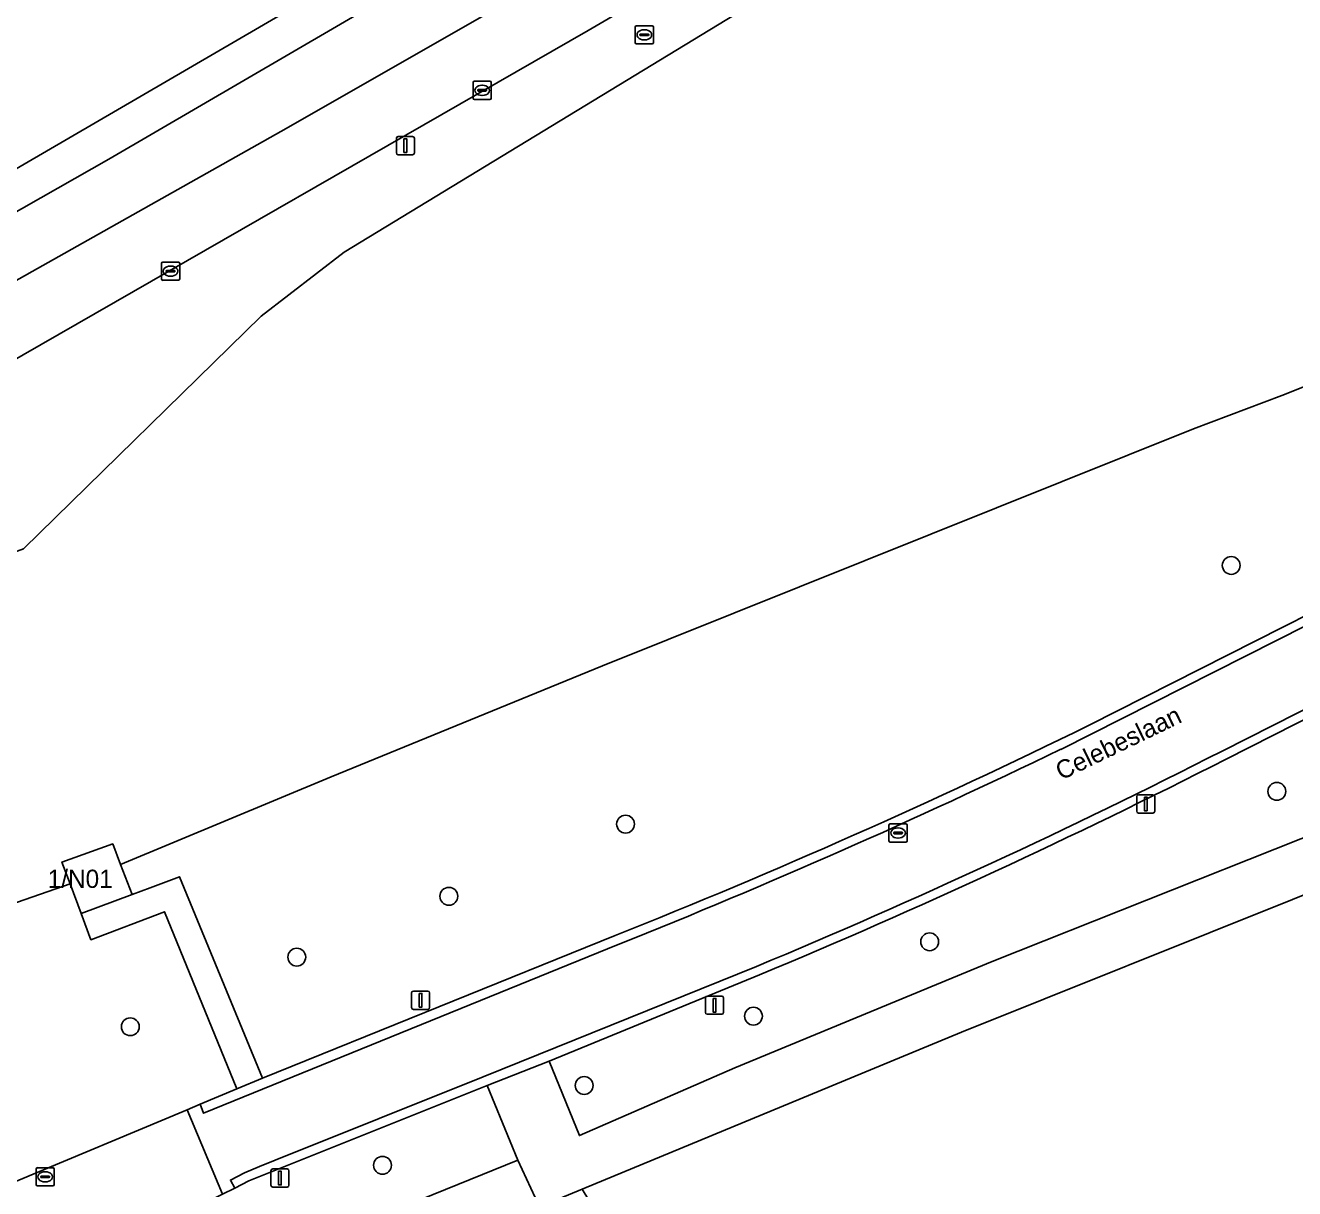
# Model space of a CAD drawing. Extents: x 162879 to 165540, y 384011 to 385181.
# Drawn here: x 163061.1 to 163130.7, y 384259.7 to 384323.5 of the extents above; entities that cross this region are included whole.
import ezdxf

# ---------------------------------------------------------------- set-up
doc = ezdxf.new("R2010")
doc.units = 0
for name, color, linetype in [('IMGEO_Berm_groen', 7, 'Continuous'), ('IMGEO_Boom', 7, 'Continuous'), ('IMGEO_Groenvoorziening', 7, 'Continuous'), ('IMGEO_Kolk', 7, 'Continuous'), ('IMGEO_Lichtmast', 7, 'Continuous'), ('IMGEO_Loofbos', 7, 'Continuous'), ('IMGEO_Openbare_ruimte_label', 7, 'Continuous'), ('IMGEO_Pand', 7, 'Continuous'), ('IMGEO_Pand_nummerreeks', 7, 'Continuous'), ('IMGEO_Rijbaan_lokaal_gesloten', 7, 'Continuous'), ('IMGEO_Rijbaan_lokaal_open', 7, 'Continuous'), ('IMGEO_Rijbaan_regionaal_gesloten', 7, 'Continuous'), ('IMGEO_Rioolput', 7, 'Continuous'), ('IMGEO_Verkeersbordpaal', 7, 'Continuous'), ('IMGEO_Voetpad_open', 7, 'Continuous')]:
    doc.layers.add(name, color=color, linetype=linetype)

msp = doc.modelspace()

# ---------------------------------------------------------------- linework, layer by layer
at = {"layer": 'IMGEO_Berm_groen'}
for points in [[(162958.296, 384257.287), (162992.107, 384275.576), (162992.774, 384275.937), (163000, 384279.879), (163047.71, 384305.906), (163065.69, 384316.128), (163134.875, 384356.468), (163142.16, 384360.715), (163149.867, 384365.229), (163197.962, 384393.395), (163222.445, 384407.821), (163353.264, 384484.905)], [(163146.789, 384293.17), (163146.364, 384293.038), (163145.533, 384292.61), (163143.634, 384291.66), (163126.98, 384283.214)], [(163101.395, 384271.38), (163089.844, 384266.648), (163091.511, 384262.562), (163100.027, 384266.274), (163114.146, 384272.104), (163148.014, 384285.572)]]:
    msp.add_lwpolyline(points, dxfattribs=at)
msp.add_lwpolyline([(163148.842, 384366.976), (163055.696, 384312.747), (162991.211, 384277.349), (162986.763, 384286.167), (162986.414, 384294.29), (162999.918, 384301.631), (163052.601, 384331.084), (163140.211, 384381.691)], close=True, dxfattribs=at)
msp.add_arc((162961.197, 384608.061), 364.705, 292.60743, 297.03711, dxfattribs=at)
at = {"layer": 'IMGEO_Boom'}
for centre in [(163127.263, 384293.838), (163129.763, 384281.443), (163094.039, 384279.646), (163084.348, 384275.687), (163110.72, 384273.192), (163076.004, 384272.35), (163101.054, 384269.112), (163066.872, 384268.531), (163091.77, 384265.308), (163080.708, 384260.93)]:
    msp.add_circle(centre, 0.489, dxfattribs=at)
at = {"layer": 'IMGEO_Groenvoorziening'}
for points in [[(163596.733, 384620.336), (163590.474, 384616.677), (163584.15, 384613.033), (163543.932, 384589.276), (163500, 384563.326), (163392.794, 384500), (163356.886, 384478.81), (163202.966, 384387.982), (163138.189, 384350.166), (163091.98, 384323.19), (163060.001, 384304.827), (163000, 384271.727), (162995.148, 384269.194), (162989.657, 384266.154), (162987.354, 384264.896)], [(162987.751, 384263.155), (162988.941, 384263.017), (163012.114, 384262.491), (163015.053, 384262.437), (163010.306, 384266.101), (163010.259, 384272.54), (163015.983, 384275.987), (163044.781, 384289.14), (163054.546, 384290.508), (163057.113, 384293.326), (163061.012, 384294.747), (163074.049, 384307.518), (163078.609, 384311.03), (163103.227, 384326.016), (163139.713, 384347.269), (163141.708, 384348.431), (163145.603, 384350.692), (163147.412, 384351.742), (163229.097, 384399.154), (163272.33, 384424.447), (163305.16, 384443.366)], [(163166.298, 384308.662), (163164.771, 384310.215), (163162.156, 384313.029), (163158.27, 384312.081), (163155.41, 384311.383), (163152.808, 384310.825), (163143.627, 384308.496), (163140.765, 384307.422), (163130.038, 384303.169), (163125.187, 384301.331), (163092.767, 384288.329), (163077.888, 384282.235), (163066.344, 384277.423), (163066.971, 384275.787), (163067.96, 384276.156), (163069.579, 384276.761), (163074.126, 384265.704), (163093.473, 384273.529)], [(163119.462, 384285.067), (163142.305, 384296.633), (163150.718, 384300.902)], [(163072.715, 384265.119), (163068.75, 384274.837), (163064.714, 384273.307), (163064.181, 384274.747), (163063.569, 384276.375), (163023.085, 384262.29), (163033.666, 384262.096), (163044.189, 384261.925), (163045.835, 384261.901), (163046.653, 384261.889)], [(163060.533, 384260.029), (163069.992, 384263.975), (163070.704, 384264.278), (163072.715, 384265.119)], [(163088.136, 384261.216), (163086.443, 384265.31), (163074.285, 384260.44), (163073.374, 384260.069), (163072.602, 384259.676), (163071.935, 384259.339), (163070.11, 384258.418), (163069.325, 384258.023), (163069.104, 384257.867)], [(163066.874, 384252.737), (163069.054, 384253.483), (163088.136, 384261.216)]]:
    msp.add_lwpolyline(points, dxfattribs=at)
msp.add_arc((162954.46, 384621.689), 374.887, 291.76571, 296.11262, dxfattribs=at)
at = {"layer": 'IMGEO_Kolk'}
for p, q in [((163085.672, 384319.474), (163085.672, 384320.326)), ((163085.747, 384320.4), (163086.599, 384320.4)), ((163086.16, 384320.18), (163086.185, 384320.18)), ((163086.673, 384320.326), (163086.673, 384319.474)), ((163086.599, 384319.4), (163085.747, 384319.4)), ((163085.931, 384319.894), (163085.931, 384319.906)), ((163086.369, 384319.857), (163085.971, 384319.857)), ((163085.974, 384319.943), (163086.372, 384319.943)), ((163086.183, 384319.62), (163086.158, 384319.62)), ((163086.415, 384319.906), (163086.415, 384319.894)), ((163068.582, 384309.553), (163068.582, 384310.405)), ((163068.657, 384310.479), (163069.509, 384310.479)), ((163069.583, 384310.405), (163069.583, 384309.553)), ((163068.841, 384309.973), (163068.841, 384309.985)), ((163069.279, 384309.936), (163068.881, 384309.936)), ((163068.884, 384310.022), (163069.282, 384310.022)), ((163069.093, 384309.699), (163069.068, 384309.699)), ((163069.07, 384310.259), (163069.095, 384310.259)), ((163069.325, 384309.985), (163069.325, 384309.973)), ((163069.509, 384309.479), (163068.657, 384309.479))]:
    msp.add_line(p, q, dxfattribs=at)
for points in [[(163085.672, 384319.474), (163085.672, 384320.326)], [(163085.747, 384320.4), (163086.599, 384320.4)], [(163086.673, 384320.326), (163086.673, 384319.474)], [(163086.599, 384319.4), (163085.747, 384319.4)], [(163068.582, 384309.553), (163068.582, 384310.405)], [(163068.657, 384310.479), (163069.509, 384310.479)], [(163069.583, 384310.405), (163069.583, 384309.553)], [(163069.509, 384309.479), (163068.657, 384309.479)]]:
    msp.add_lwpolyline(points, dxfattribs=at)
for centre, radius, start, end in [((163085.749, 384320.324), 0.0765, 91.55205, 178.44795), ((163085.749, 384320.324), 0.0765, 91.55205, 178.44795), ((163086.597, 384320.324), 0.0765, 1.55205, 88.44795), ((163086.597, 384320.324), 0.0765, 1.55205, 88.44795), ((163085.749, 384319.476), 0.0765, 181.55205, 268.44795), ((163085.749, 384319.476), 0.0765, 181.55205, 268.44795), ((163085.971, 384319.903), 0.0403, 85.87752, 175.75265), ((163085.968, 384319.893), 0.0366, 178.93798, 274.71019), ((163086.372, 384319.9), 0.043, 264.86636, 352.45326), ((163086.376, 384319.905), 0.0386, 1.73085, 96.63898), ((163086.597, 384319.476), 0.0765, 271.55205, 358.44795), ((163086.597, 384319.476), 0.0765, 271.55205, 358.44795), ((163068.659, 384310.403), 0.0765, 91.55205, 178.44795), ((163068.659, 384310.403), 0.0765, 91.55205, 178.44795), ((163069.507, 384310.403), 0.0765, 1.55205, 88.44795), ((163069.507, 384310.403), 0.0765, 1.55205, 88.44795), ((163068.881, 384309.982), 0.0403, 85.87752, 175.75265), ((163068.878, 384309.972), 0.0366, 178.93798, 274.71019), ((163069.282, 384309.979), 0.043, 264.86636, 352.45326), ((163069.286, 384309.984), 0.0386, 1.73085, 96.63898), ((163068.659, 384309.555), 0.0765, 181.55205, 268.44795), ((163068.659, 384309.555), 0.0765, 181.55205, 268.44795), ((163069.507, 384309.555), 0.0765, 271.55205, 358.44795), ((163069.507, 384309.555), 0.0765, 271.55205, 358.44795)]:
    msp.add_arc(centre, radius, start, end, dxfattribs=at)
for centre, major_axis, ratio, start_param, end_param in [((163086.159, 384319.9), (-0.387, 0.002), 0.722429, 4.712389, 7.853982), ((163086.184, 384319.9), (-0.39, 0.002), 0.717154, 1.570796, 4.712389), ((163069.069, 384309.979), (-0.387, 0.002), 0.722429, 4.712389, 7.853982), ((163069.094, 384309.979), (-0.39, 0.002), 0.717154, 1.570796, 4.712389)]:
    msp.add_ellipse(centre, major_axis=major_axis, ratio=ratio, start_param=start_param, end_param=end_param, dxfattribs=at)
at = {"layer": 'IMGEO_Lichtmast'}
for p, q in [((163081.566, 384317.37), (163082.356, 384317.37)), ((163082.356, 384317.37), (163081.566, 384317.37)), ((163081.466, 384316.47), (163081.466, 384317.27)), ((163081.466, 384317.27), (163081.466, 384316.47)), ((163082.456, 384317.27), (163082.456, 384316.47)), ((163082.456, 384316.47), (163082.456, 384317.27)), ((163082.356, 384316.37), (163081.566, 384316.37)), ((163081.566, 384316.37), (163082.356, 384316.37)), ((163122.081, 384280.356), (163122.081, 384281.156)), ((163122.081, 384281.156), (163122.081, 384280.356)), ((163122.181, 384281.256), (163122.971, 384281.256)), ((163122.971, 384281.256), (163122.181, 384281.256)), ((163123.071, 384281.156), (163123.071, 384280.356)), ((163123.071, 384280.356), (163123.071, 384281.156)), ((163122.971, 384280.256), (163122.181, 384280.256)), ((163122.181, 384280.256), (163122.971, 384280.256)), ((163098.422, 384269.312), (163098.422, 384270.112)), ((163098.422, 384270.112), (163098.422, 384269.312)), ((163098.522, 384270.212), (163099.312, 384270.212)), ((163099.312, 384270.212), (163098.522, 384270.212)), ((163099.412, 384270.112), (163099.412, 384269.312)), ((163099.412, 384269.312), (163099.412, 384270.112)), ((163099.312, 384269.212), (163098.522, 384269.212)), ((163098.522, 384269.212), (163099.312, 384269.212)), ((163074.587, 384259.832), (163074.587, 384260.632)), ((163074.587, 384260.632), (163074.587, 384259.832)), ((163074.687, 384260.732), (163075.477, 384260.732)), ((163075.477, 384260.732), (163074.687, 384260.732)), ((163075.577, 384260.632), (163075.577, 384259.832)), ((163075.577, 384259.832), (163075.577, 384260.632)), ((163075.477, 384259.732), (163074.687, 384259.732)), ((163074.687, 384259.732), (163075.477, 384259.732))]:
    msp.add_line(p, q, dxfattribs=at)
for points in [[(163081.886, 384317.245), (163082.036, 384317.245), (163082.036, 384316.495), (163081.886, 384316.495), (163081.886, 384317.245)], [(163122.501, 384281.131), (163122.651, 384281.131), (163122.651, 384280.381), (163122.501, 384280.381), (163122.501, 384281.131)], [(163098.842, 384270.087), (163098.992, 384270.087), (163098.992, 384269.337), (163098.842, 384269.337), (163098.842, 384270.087)], [(163075.007, 384260.607), (163075.157, 384260.607), (163075.157, 384259.857), (163075.007, 384259.857), (163075.007, 384260.607)]]:
    msp.add_lwpolyline(points, dxfattribs=at)
for centre, start, end in [((163081.566, 384317.27), 90, 180), ((163081.566, 384317.27), 90, 180), ((163082.356, 384317.27), 0, 90), ((163082.356, 384317.27), 360, 90), ((163081.566, 384316.47), 180, 270), ((163081.566, 384316.47), 180, 270), ((163082.356, 384316.47), 270, 0), ((163082.356, 384316.47), 270, 0), ((163122.181, 384281.156), 90, 180), ((163122.181, 384281.156), 90, 180), ((163122.971, 384281.156), 0, 90), ((163122.971, 384281.156), 360, 90), ((163122.181, 384280.356), 180, 270), ((163122.181, 384280.356), 180, 270), ((163122.971, 384280.356), 270, 0), ((163122.971, 384280.356), 270, 0), ((163098.522, 384270.112), 90, 180), ((163098.522, 384270.112), 90, 180), ((163099.312, 384270.112), 0, 90), ((163099.312, 384270.112), 360, 90), ((163098.522, 384269.312), 180, 270), ((163098.522, 384269.312), 180, 270), ((163099.312, 384269.312), 270, 0), ((163099.312, 384269.312), 270, 0), ((163074.687, 384260.632), 90, 180), ((163074.687, 384260.632), 90, 180), ((163075.477, 384260.632), 0, 90), ((163075.477, 384260.632), 360, 90), ((163074.687, 384259.832), 180, 270), ((163074.687, 384259.832), 180, 270), ((163075.477, 384259.832), 270, 0), ((163075.477, 384259.832), 270, 0)]:
    msp.add_arc(centre, 0.1, start, end, dxfattribs=at)
at = {"layer": 'IMGEO_Loofbos'}
for points in [[(163140.211, 384381.691), (163052.601, 384331.084), (162999.918, 384301.631), (162986.414, 384294.29), (162986.763, 384286.167), (162991.211, 384277.349), (163055.696, 384312.747), (163148.842, 384366.976)], [(163155.934, 384258.131), (163155.116, 384260.952), (163148.784, 384282.785), (163112.465, 384268.23), (163091.662, 384259.624), (163097.491, 384250), (163105.946, 384236.061), (163109.025, 384230.235), (163114.501, 384233.625), (163136.641, 384247.33), (163140.262, 384250), (163143.861, 384252.646)]]:
    msp.add_lwpolyline(points, close=True, dxfattribs=at)
msp.add_lwpolyline([(163139.713, 384347.269), (163103.227, 384326.016), (163078.609, 384311.03), (163074.049, 384307.518), (163061.012, 384294.747), (163057.113, 384293.326), (163054.546, 384290.508), (163044.781, 384289.14), (163015.983, 384275.987), (163010.259, 384272.54), (163010.306, 384266.101), (163015.053, 384262.437), (163023.085, 384262.29), (163063.569, 384276.375), (163063.122, 384277.562), (163065.907, 384278.563), (163066.344, 384277.423), (163077.888, 384282.235), (163092.767, 384288.329), (163125.187, 384301.331), (163130.038, 384303.169), (163140.765, 384307.422)], dxfattribs=at)
at = {"layer": 'IMGEO_Pand'}
msp.add_lwpolyline([(163066.344, 384277.423), (163065.907, 384278.563), (163063.122, 384277.562), (163063.569, 384276.375), (163064.181, 384274.747), (163066.971, 384275.787)], close=True, dxfattribs=at)
at = {"layer": 'IMGEO_Rijbaan_lokaal_gesloten'}
for points in [[(163143.365, 384292.054), (163141.531, 384295.681), (163117.918, 384283.749)], [(163126.767, 384283.656), (163143.365, 384292.054)], [(163093.642, 384273.04), (163070.882, 384263.789), (163070.704, 384264.278), (163069.992, 384263.975), (163071.935, 384259.339), (163072.602, 384259.676), (163072.365, 384260.115), (163073.136, 384260.517), (163073.968, 384260.869), (163074.82, 384261.212), (163086.237, 384265.783), (163101.219, 384271.839)]]:
    msp.add_lwpolyline(points, dxfattribs=at)
msp.add_lwpolyline([(163069.325, 384258.023), (163070.11, 384258.418), (163071.935, 384259.339), (163069.992, 384263.975), (163060.533, 384260.029), (163050.998, 384256.102), (163049.129, 384255.319), (163048.235, 384254.869), (163047.128, 384254.295), (163035.025, 384248.253), (163031.406, 384246.417), (163034.42, 384240.509), (163038.44, 384242.526), (163056.687, 384251.652)], close=True, dxfattribs=at)
for centre, radius, start, end in [((162951.566, 384627.979), 382.318, 291.81539, 295.79255), ((162961.001, 384608.513), 364.706, 292.61084, 297.03412)]:
    msp.add_arc(centre, radius, start, end, dxfattribs=at)
at = {"layer": 'IMGEO_Rijbaan_lokaal_open'}
for points in [[(163161.368, 384306.288), (163152.507, 384301.843), (163150.718, 384300.902), (163142.305, 384296.633), (163119.462, 384285.067)], [(163172.552, 384306.5), (163164.703, 384302.899), (163163.382, 384302.252), (163162.739, 384301.938), (163159.882, 384300.503), (163153.951, 384297.527), (163152.765, 384296.875), (163143.423, 384292.083), (163143.365, 384292.054), (163126.767, 384283.656)], [(163117.918, 384283.749), (163141.531, 384295.681), (163150.915, 384300.439), (163152.679, 384301.369), (163161.622, 384305.861)], [(163126.98, 384283.214), (163143.634, 384291.66)], [(163093.473, 384273.529), (163074.126, 384265.704), (163072.715, 384265.119), (163070.704, 384264.278), (163070.882, 384263.789), (163093.642, 384273.04)], [(163101.219, 384271.839), (163086.237, 384265.783), (163074.82, 384261.212), (163073.968, 384260.869), (163073.136, 384260.517), (163072.365, 384260.115), (163072.602, 384259.676), (163073.374, 384260.069), (163074.285, 384260.44), (163086.443, 384265.31), (163089.844, 384266.648), (163101.395, 384271.38)]]:
    msp.add_lwpolyline(points, dxfattribs=at)
for centre, radius, start, end in [((162954.46, 384621.689), 374.887, 291.76571, 296.11262), ((162951.566, 384627.979), 382.318, 291.81539, 295.79255), ((162961.001, 384608.513), 364.706, 292.61084, 297.03412), ((162961.197, 384608.061), 364.705, 292.60743, 297.03711)]:
    msp.add_arc(centre, radius, start, end, dxfattribs=at)
at = {"layer": 'IMGEO_Rijbaan_regionaal_gesloten'}
for points in [[(163075.431, 384317.808), (163102.908, 384333.537), (163136.085, 384353.074), (163136.524, 384353.333), (163134.875, 384356.468), (163065.69, 384316.128), (163047.71, 384305.906), (163000, 384279.879), (162992.774, 384275.937), (162992.107, 384275.576), (162958.296, 384257.287)], [(163060.001, 384304.827), (163091.98, 384323.19), (163138.189, 384350.166), (163136.524, 384353.333), (163136.085, 384353.074), (163102.908, 384333.537), (163075.431, 384317.808), (163019.119, 384286.121), (162984.518, 384267.432), (162966.682, 384257.842), (162956.166, 384251.683), (162950.166, 384247.581), (162946.914, 384245.082), (162943.802, 384242.49), (162940.823, 384239.608), (162938.038, 384236.628), (162940.725, 384234.294)], [(162937.637, 384241.374), (162932.679, 384236.006), (162916.515, 384218.506), (162915.908, 384217.643), (162913.326, 384214.826), (162913.538, 384209.756), (162921.56, 384218.689), (162929.746, 384227.688), (162935.296, 384233.694), (162938.038, 384236.628), (162940.823, 384239.608), (162943.802, 384242.49), (162946.914, 384245.082), (162950.166, 384247.581), (162956.166, 384251.683), (162966.682, 384257.842), (162984.518, 384267.432), (163019.119, 384286.121), (163075.431, 384317.808)]]:
    msp.add_lwpolyline(points, dxfattribs=at)
at = {"layer": 'IMGEO_Rioolput'}
for p, q in [((163094.569, 384322.522), (163094.569, 384323.374)), ((163094.644, 384323.448), (163095.496, 384323.448)), ((163094.828, 384322.942), (163094.828, 384322.954)), ((163095.266, 384322.905), (163094.868, 384322.905)), ((163094.871, 384322.991), (163095.269, 384322.991)), ((163095.057, 384323.228), (163095.082, 384323.228)), ((163095.312, 384322.954), (163095.312, 384322.942)), ((163095.57, 384323.374), (163095.57, 384322.522)), ((163095.496, 384322.448), (163094.644, 384322.448)), ((163095.08, 384322.668), (163095.055, 384322.668)), ((163108.488, 384278.735), (163108.488, 384279.587)), ((163108.563, 384279.661), (163109.415, 384279.661)), ((163108.747, 384279.155), (163108.747, 384279.167)), ((163109.185, 384279.118), (163108.787, 384279.118)), ((163108.79, 384279.204), (163109.188, 384279.204)), ((163108.976, 384279.441), (163109.001, 384279.441)), ((163109.231, 384279.167), (163109.231, 384279.155)), ((163109.489, 384279.587), (163109.489, 384278.735)), ((163109.415, 384278.661), (163108.563, 384278.661)), ((163108.999, 384278.881), (163108.974, 384278.881)), ((163061.702, 384259.873), (163061.702, 384260.725)), ((163061.777, 384260.799), (163062.629, 384260.799)), ((163061.961, 384260.293), (163061.961, 384260.305)), ((163062.399, 384260.256), (163062.001, 384260.256)), ((163062.004, 384260.342), (163062.402, 384260.342)), ((163062.19, 384260.579), (163062.215, 384260.579)), ((163062.445, 384260.305), (163062.445, 384260.293)), ((163062.703, 384260.725), (163062.703, 384259.873)), ((163062.629, 384259.799), (163061.777, 384259.799)), ((163062.213, 384260.019), (163062.188, 384260.019))]:
    msp.add_line(p, q, dxfattribs=at)
for points in [[(163094.569, 384322.522), (163094.569, 384323.374)], [(163094.644, 384323.448), (163095.496, 384323.448)], [(163095.57, 384323.374), (163095.57, 384322.522)], [(163095.496, 384322.448), (163094.644, 384322.448)], [(163108.488, 384278.735), (163108.488, 384279.587)], [(163108.563, 384279.661), (163109.415, 384279.661)], [(163109.489, 384279.587), (163109.489, 384278.735)], [(163109.415, 384278.661), (163108.563, 384278.661)], [(163061.702, 384259.873), (163061.702, 384260.725)], [(163061.777, 384260.799), (163062.629, 384260.799)], [(163062.703, 384260.725), (163062.703, 384259.873)], [(163062.629, 384259.799), (163061.777, 384259.799)]]:
    msp.add_lwpolyline(points, dxfattribs=at)
for centre, radius, start, end in [((163094.646, 384323.372), 0.0765, 91.55205, 178.44795), ((163094.646, 384323.372), 0.0765, 91.55205, 178.44795), ((163094.868, 384322.951), 0.0403, 85.87752, 175.75265), ((163094.865, 384322.941), 0.0366, 178.93798, 274.71019), ((163095.269, 384322.948), 0.043, 264.86636, 352.45326), ((163095.273, 384322.953), 0.0386, 1.73085, 96.63898), ((163095.494, 384323.372), 0.0765, 1.55205, 88.44795), ((163095.494, 384323.372), 0.0765, 1.55205, 88.44795), ((163094.646, 384322.524), 0.0765, 181.55205, 268.44795), ((163094.646, 384322.524), 0.0765, 181.55205, 268.44795), ((163095.494, 384322.524), 0.0765, 271.55205, 358.44795), ((163095.494, 384322.524), 0.0765, 271.55205, 358.44795), ((163108.565, 384279.585), 0.0765, 91.55205, 178.44795), ((163108.565, 384279.585), 0.0765, 91.55205, 178.44795), ((163108.787, 384279.164), 0.0403, 85.87752, 175.75265), ((163108.784, 384279.154), 0.0366, 178.93798, 274.71019), ((163109.188, 384279.161), 0.043, 264.86636, 352.45326), ((163109.192, 384279.166), 0.0386, 1.73085, 96.63898), ((163109.413, 384279.585), 0.0765, 1.55205, 88.44795), ((163109.413, 384279.585), 0.0765, 1.55205, 88.44795), ((163108.565, 384278.737), 0.0765, 181.55205, 268.44795), ((163108.565, 384278.737), 0.0765, 181.55205, 268.44795), ((163109.413, 384278.737), 0.0765, 271.55205, 358.44795), ((163109.413, 384278.737), 0.0765, 271.55205, 358.44795), ((163061.779, 384260.723), 0.0765, 91.55205, 178.44795), ((163061.779, 384260.723), 0.0765, 91.55205, 178.44795), ((163062.001, 384260.302), 0.0403, 85.87752, 175.75265), ((163061.998, 384260.292), 0.0366, 178.93798, 274.71019), ((163062.402, 384260.299), 0.043, 264.86636, 352.45326), ((163062.406, 384260.304), 0.0386, 1.73085, 96.63898), ((163062.627, 384260.723), 0.0765, 1.55205, 88.44795), ((163062.627, 384260.723), 0.0765, 1.55205, 88.44795), ((163061.779, 384259.875), 0.0765, 181.55205, 268.44795), ((163061.779, 384259.875), 0.0765, 181.55205, 268.44795), ((163062.627, 384259.875), 0.0765, 271.55205, 358.44795), ((163062.627, 384259.875), 0.0765, 271.55205, 358.44795)]:
    msp.add_arc(centre, radius, start, end, dxfattribs=at)
for centre, major_axis, ratio, start_param, end_param in [((163095.056, 384322.948), (-0.387, 0.002), 0.722429, 4.712389, 7.853982), ((163095.081, 384322.948), (-0.39, 0.002), 0.717154, 1.570796, 4.712389), ((163108.975, 384279.161), (-0.387, 0.002), 0.722429, 4.712389, 7.853982), ((163109, 384279.161), (-0.39, 0.002), 0.717154, 1.570796, 4.712389), ((163062.189, 384260.299), (-0.387, 0.002), 0.722429, 4.712389, 7.853982), ((163062.214, 384260.299), (-0.39, 0.002), 0.717154, 1.570796, 4.712389)]:
    msp.add_ellipse(centre, major_axis=major_axis, ratio=ratio, start_param=start_param, end_param=end_param, dxfattribs=at)
at = {"layer": 'IMGEO_Verkeersbordpaal'}
for p, q in [((163082.302, 384269.585), (163082.302, 384270.385)), ((163082.302, 384270.385), (163082.302, 384269.585)), ((163082.402, 384270.485), (163083.192, 384270.485)), ((163083.192, 384270.485), (163082.402, 384270.485)), ((163083.292, 384270.385), (163083.292, 384269.585)), ((163083.292, 384269.585), (163083.292, 384270.385)), ((163083.192, 384269.485), (163082.402, 384269.485)), ((163082.402, 384269.485), (163083.192, 384269.485))]:
    msp.add_line(p, q, dxfattribs=at)
msp.add_lwpolyline([(163082.722, 384270.36), (163082.872, 384270.36), (163082.872, 384269.61), (163082.722, 384269.61), (163082.722, 384270.36)], dxfattribs=at)
for centre, start, end in [((163082.402, 384270.385), 90, 180), ((163082.402, 384270.385), 90, 180), ((163083.192, 384270.385), 0, 90), ((163083.192, 384270.385), 360, 90), ((163082.402, 384269.585), 180, 270), ((163082.402, 384269.585), 180, 270), ((163083.192, 384269.585), 270, 0), ((163083.192, 384269.585), 270, 0)]:
    msp.add_arc(centre, 0.1, start, end, dxfattribs=at)
at = {"layer": 'IMGEO_Voetpad_open'}
for points in [[(163148.784, 384282.785), (163154.745, 384282.736), (163153.346, 384287.562), (163148.014, 384285.572), (163114.146, 384272.104), (163100.027, 384266.274), (163091.511, 384262.562), (163089.844, 384266.648), (163086.443, 384265.31), (163088.136, 384261.216), (163089.311, 384258.655), (163091.662, 384259.624), (163112.465, 384268.23)], [(163066.971, 384275.787), (163064.181, 384274.747), (163064.714, 384273.307), (163068.75, 384274.837), (163072.715, 384265.119), (163074.126, 384265.704), (163069.579, 384276.761), (163067.96, 384276.156)]]:
    msp.add_lwpolyline(points, close=True, dxfattribs=at)
msp.add_lwpolyline([(163089.311, 384258.655), (163088.136, 384261.216), (163069.054, 384253.483), (163066.874, 384252.737)], dxfattribs=at)

# ---------------------------------------------------------------- texts
at = {"layer": 'IMGEO_Openbare_ruimte_label'}
msp.add_text('Celebeslaan', height=1, rotation=25.77111, dxfattribs=at).set_placement((163117.937, 384282.035))
at = {"layer": 'IMGEO_Pand_nummerreeks'}
msp.add_text('1/N01', height=1, dxfattribs=at).set_placement((163062.34, 384276.147))

doc.saveas('drawing.dxf')
